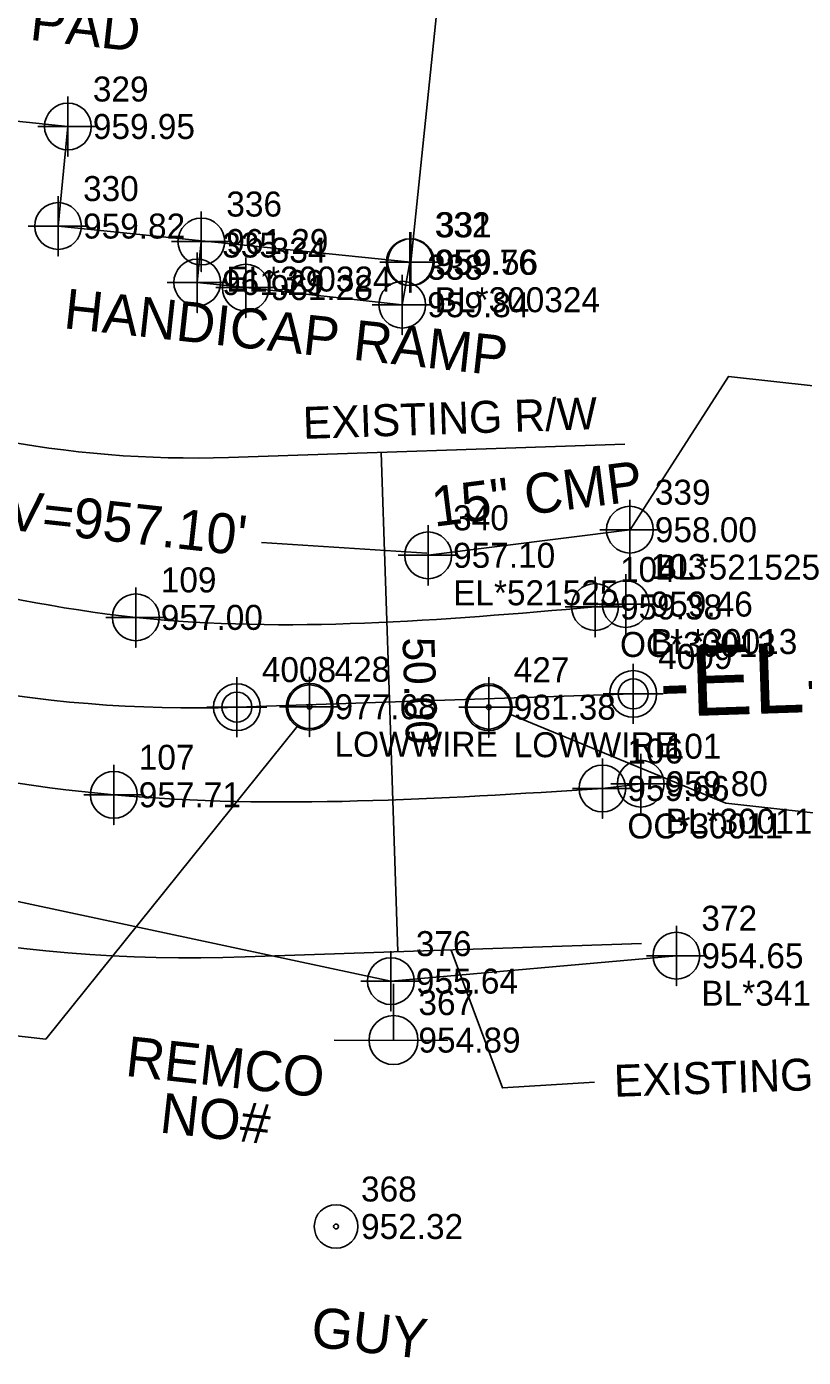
# Model space of a CAD drawing. Extents: x 1150279 to 1151282, y 654632 to 657999.
# Drawn here: x 1150999.3 to 1151077.1, y 657002 to 657135.2 of the extents above; entities that cross this region are included whole.
import ezdxf

# ---------------------------------------------------------------- set-up
doc = ezdxf.new("R2010")
doc.units = 0
for name, color, linetype in [('COGO Default Chain', 7, 'Continuous'), ('COGO Default Curve', 7, 'Continuous'), ('Cogo Default Point CELL', 7, 'Continuous'), ('COGO Default Point Number', 7, 'Continuous'), ('Default Symbol CELL', 7, 'Continuous'), ('Default Symbol Cogo Comment', 7, 'Continuous'), ('Default Symbol Cogo Elevation', 7, 'Continuous'), ('Default Symbol Cogo Number', 7, 'Continuous'), ('Exist Building', 7, 'Continuous'), ('Exist Building Cogo Elevation', 7, 'Continuous'), ('Exist Building Cogo Number', 7, 'Continuous'), ('Exist Building Cogo Point CELL', 7, 'Continuous'), ('Exist Horizontal Alignment', 7, 'Continuous'), ('Exist Horizontal Alignment Direction Label', 7, 'Continuous'), ('Exist Horizontal Alignment Station Label', 7, 'Continuous'), ('Exist Other Culture Anchor (Guy Wire) CELL', 7, 'Continuous'), ('Exist Other Culture Anchor (Guy Wire) Cogo Elevation', 7, 'Continuous'), ('Exist Other Culture Anchor (Guy Wire) Cogo Number', 7, 'Continuous'), ('Exist Other Culture Fence Line', 7, 'Continuous'), ('Exist Other Culture Fence Line Cogo Comment', 7, 'Continuous'), ('Exist Other Culture Fence Line Cogo Elevation', 7, 'Continuous'), ('Exist Other Culture Fence Line Cogo Number', 7, 'Continuous'), ('Exist Other Culture Fence Line Cogo Point CELL', 7, 'Continuous'), ('Exist Right of Way Line', 7, 'Continuous'), ('Exist Right of Way Line Leader', 7, 'Continuous'), ('Exist Right of Way Line Text', 7, 'Continuous'), ('Exist Right of Way Width CELL', 7, 'Continuous'), ('Exist Roads EOP', 7, 'Continuous'), ('Exist Roads EOP Cogo Comment', 7, 'Continuous'), ('Exist Roads EOP Cogo Elevation', 7, 'Continuous'), ('Exist Roads EOP Cogo Number', 7, 'Continuous'), ('Exist Roads EOP Cogo Point CELL', 7, 'Continuous'), ('Exist Roads EOP Other', 7, 'Continuous'), ('Exist Roads EOP Other Cogo Comment', 7, 'Continuous'), ('Exist Roads EOP Other Cogo Elevation', 7, 'Continuous'), ('Exist Roads EOP Other Cogo Number', 7, 'Continuous'), ('Exist Roads EOP Other Cogo Point CELL', 7, 'Continuous'), ('Exist Roads EOP Other Text', 7, 'Continuous'), ('Exist Roads EOP Text', 7, 'Continuous'), ('Exist Structure Minor Pipes CMP 15 Inch', 7, 'Continuous'), ('Exist Structure Minor Pipes CMP 15 Inch Cogo Comment', 7, 'Continuous'), ('Exist Structure Minor Pipes CMP 15 Inch Cogo Elevation', 7, 'Continuous'), ('Exist Structure Minor Pipes CMP 15 Inch Cogo Number', 7, 'Continuous'), ('Exist Structure Minor Pipes CMP 15 Inch Cogo Point CELL', 7, 'Continuous'), ('Exist Structure Minor Pipes CMP 15 Inch Leader', 7, 'Continuous'), ('Exist Structure Minor Pipes CMP 15 Inch Text', 7, 'Continuous'), ('Exist Utilities Other Located Object CELL', 7, 'Continuous'), ('Exist Utilities Other Located Object Leader', 7, 'Continuous'), ('Exist Utilities Power Joint Use Telephone CELL', 7, 'Continuous'), ('Exist Utilities Power Joint Use Telephone Cogo Elevation', 7, 'Continuous'), ('Exist Utilities Power Joint Use Telephone Cogo Number', 7, 'Continuous'), ('Exist Utilities Power Joint Use Telephone Text', 7, 'Continuous')]:
    doc.layers.add(name, color=color, linetype=linetype)

msp = doc.modelspace()

# ---------------------------------------------------------------- linework, layer by layer
at = {"layer": 'COGO Default Chain'}
msp.add_line((1151020.37, 657067.07), (1151060.05, 657068.39), dxfattribs=at)
msp.add_arc((1151016.01, 657196.99), 130, 245.6804, 271.9187, dxfattribs=at)
at = {"layer": 'COGO Default Curve'}
msp.add_arc((1151016.01, 657196.99), 130, 245.6804, 271.9187, dxfattribs=at)
at = {"layer": 'Cogo Default Point CELL'}
for points in [[(1151060.05, 657071.39), (1151060.05, 657068.39)], [(1151020.37, 657070.07), (1151020.37, 657067.07)], [(1151020.37, 657070.07), (1151020.37, 657067.07)], [(1151057.05, 657068.39), (1151060.05, 657068.39)], [(1151060.05, 657068.39), (1151063.05, 657068.39)], [(1151060.05, 657068.39), (1151060.05, 657065.39)], [(1151017.37, 657067.07), (1151020.37, 657067.07)], [(1151017.37, 657067.07), (1151020.37, 657067.07)], [(1151020.37, 657067.07), (1151023.37, 657067.07)], [(1151020.37, 657067.07), (1151020.37, 657064.07)], [(1151020.37, 657067.07), (1151023.37, 657067.07)], [(1151020.37, 657067.07), (1151020.37, 657064.07)]]:
    msp.add_lwpolyline(points, dxfattribs=at)
for centre in [(1151060.05, 657068.39), (1151020.37, 657067.07), (1151020.37, 657067.07)]:
    msp.add_circle(centre, 2.34, dxfattribs=at)
at = {"layer": 'Default Symbol CELL'}
for points in [[(1151027.65, 657070.11), (1151027.65, 657064.11), (1151027.65, 657067.11), (1151030.65, 657067.11), (1151024.65, 657067.11)], [(1151045.59, 657070.06), (1151045.59, 657064.06), (1151045.59, 657067.06), (1151048.59, 657067.06), (1151042.59, 657067.06)]]:
    msp.add_lwpolyline(points, dxfattribs=at)
for centre in [(1151027.65, 657067.11), (1151045.59, 657067.06)]:
    msp.add_circle(centre, 2.34, dxfattribs=at)
at = {"layer": 'Exist Building'}
msp.add_lwpolyline([(1150963.17, 657162.3), (1150962, 657151.2), (1150955.74, 657152.17), (1150954.56, 657141.15), (1150960.94, 657140.6), (1150959.8, 657129.69), (1151003.45, 657125.16), (1151002.47, 657115.2), (1151037.8, 657111.58), (1151043.24, 657164.14)], dxfattribs=at)
at = {"layer": 'Exist Building Cogo Point CELL'}
for points in [[(1151003.45, 657128.16), (1151003.45, 657122.16), (1151003.45, 657125.16), (1151006.45, 657125.16), (1151000.45, 657125.16)], [(1151002.47, 657118.2), (1151002.47, 657112.2), (1151002.47, 657115.2), (1151005.47, 657115.2), (1150999.47, 657115.2)], [(1151037.8, 657114.58), (1151037.8, 657108.58), (1151037.8, 657111.58), (1151040.8, 657111.58), (1151034.8, 657111.58)]]:
    msp.add_lwpolyline(points, dxfattribs=at)
for centre in [(1151003.45, 657125.16), (1151002.47, 657115.2), (1151037.8, 657111.58)]:
    msp.add_circle(centre, 2.34, dxfattribs=at)
at = {"layer": 'Exist Horizontal Alignment'}
msp.add_line((1151020.37, 657067.07), (1151060.05, 657068.39), dxfattribs=at)
msp.add_arc((1151016.01, 657196.99), 130, 245.6804, 271.9187, dxfattribs=at)
at = {"layer": 'Exist Horizontal Alignment Station Label'}
for centre in [(1151060.05, 657068.39), (1151020.37, 657067.07)]:
    msp.add_circle(centre, 1.5, dxfattribs=at)
at = {"layer": 'Exist Other Culture Anchor (Guy Wire) CELL'}
for radius in [2.18, 0.24]:
    msp.add_circle((1151030.3, 657015.11), radius, dxfattribs=at)
at = {"layer": 'Exist Other Culture Fence Line'}
msp.add_lwpolyline([(1151064.38, 657042.2), (1151035.79, 657039.66), (1150986.53, 657050.15), (1150941.42, 657063.2), (1150898.39, 657078.65), (1150854.86, 657094.99), (1150825.03, 657100.53), (1150812.46, 657091.59), (1150835.17, 657043.74), (1150852.72, 657007.43)], dxfattribs=at)
at = {"layer": 'Exist Other Culture Fence Line Cogo Point CELL'}
for points in [[(1151064.38, 657045.2), (1151064.38, 657039.2), (1151064.38, 657042.2), (1151067.38, 657042.2), (1151061.38, 657042.2)], [(1151035.79, 657042.66), (1151035.79, 657036.66), (1151035.79, 657039.66), (1151038.79, 657039.66), (1151032.79, 657039.66)]]:
    msp.add_lwpolyline(points, dxfattribs=at)
for centre in [(1151064.38, 657042.2), (1151035.79, 657039.66)]:
    msp.add_circle(centre, 2.34, dxfattribs=at)
at = {"layer": 'Exist Right of Way Line'}
for p, q in [((1151019.53, 657092.05), (1151059.22, 657093.38)), ((1151021.2, 657042.08), (1151060.89, 657043.41))]:
    msp.add_line(p, q, dxfattribs=at)
for radius in [105, 155]:
    msp.add_arc((1151016.01, 657196.99), radius, 245.6804, 271.9187, dxfattribs=at)
at = {"layer": 'Exist Right of Way Line Leader'}
msp.add_lwpolyline([(1151041.84, 657042.77), (1151046.96, 657028.97), (1151056.17, 657029.54)], dxfattribs=at)
at = {"layer": 'Exist Right of Way Width CELL'}
for p in [(1151034.81, 657092.56), (1151036.48, 657042.59)]:
    msp.add_line(p, (1151035.67, 657066.81), dxfattribs=at)
at = {"layer": 'Exist Roads EOP'}
for p, q in [((1151059.3, 657077.38), (1151056.23, 657077.09)), ((1151060.81, 657059.41), (1151056.97, 657058.93))]:
    msp.add_line(p, q, dxfattribs=at)
for points in [[(1151056.23, 657077.09), (1151010.25, 657076.05), (1150965.32, 657087.79), (1150920.52, 657109.03), (1150919.16, 657109.82)], [(1151056.97, 657058.93), (1151008.05, 657058.3), (1150957.78, 657070.1), (1150911.09, 657090.11), (1150910.09, 657090.54)]]:
    msp.add_spline(points, degree=3, dxfattribs=at)
at = {"layer": 'Exist Roads EOP Cogo Point CELL'}
for points in [[(1151056.23, 657080.09), (1151056.23, 657074.09), (1151056.23, 657077.09), (1151059.23, 657077.09), (1151053.23, 657077.09)], [(1151059.3, 657080.38), (1151059.3, 657074.38), (1151059.3, 657077.38), (1151062.3, 657077.38), (1151056.3, 657077.38)], [(1151010.25, 657079.05), (1151010.25, 657073.05), (1151010.25, 657076.05), (1151013.25, 657076.05), (1151007.25, 657076.05)], [(1151056.97, 657061.93), (1151056.97, 657055.93), (1151056.97, 657058.93), (1151059.97, 657058.93), (1151053.97, 657058.93)], [(1151060.81, 657062.41), (1151060.81, 657056.41), (1151060.81, 657059.41), (1151063.81, 657059.41), (1151057.81, 657059.41)], [(1151008.05, 657061.3), (1151008.05, 657055.3), (1151008.05, 657058.3), (1151011.05, 657058.3), (1151005.05, 657058.3)]]:
    msp.add_lwpolyline(points, dxfattribs=at)
for centre in [(1151056.23, 657077.09), (1151059.3, 657077.38), (1151010.25, 657076.05), (1151008.05, 657058.3), (1151056.97, 657058.93), (1151060.81, 657059.41)]:
    msp.add_circle(centre, 2.34, dxfattribs=at)
at = {"layer": 'Exist Roads EOP Other'}
msp.add_lwpolyline([(1151037.68, 657111.58), (1151036.93, 657107.33), (1151021.26, 657109.04), (1151016.4, 657109.55), (1151016.81, 657113.65)], dxfattribs=at)
at = {"layer": 'Exist Roads EOP Other Cogo Point CELL'}
for points in [[(1151016.81, 657116.65), (1151016.81, 657110.65), (1151016.81, 657113.65), (1151019.81, 657113.65), (1151013.81, 657113.65)], [(1151037.68, 657114.58), (1151037.68, 657108.58), (1151037.68, 657111.58), (1151040.68, 657111.58), (1151034.68, 657111.58)], [(1151016.4, 657112.55), (1151016.4, 657106.55), (1151016.4, 657109.55), (1151019.4, 657109.55), (1151013.4, 657109.55)], [(1151021.26, 657112.04), (1151021.26, 657106.04), (1151021.26, 657109.04), (1151024.26, 657109.04), (1151018.26, 657109.04)], [(1151036.93, 657110.33), (1151036.93, 657104.33), (1151036.93, 657107.33), (1151039.93, 657107.33), (1151033.93, 657107.33)]]:
    msp.add_lwpolyline(points, dxfattribs=at)
for centre in [(1151016.81, 657113.65), (1151037.68, 657111.58), (1151016.4, 657109.55), (1151021.26, 657109.04), (1151036.93, 657107.33)]:
    msp.add_circle(centre, 2.34, dxfattribs=at)
at = {"layer": 'Exist Structure Minor Pipes CMP 15 Inch'}
msp.add_line((1151059.72, 657084.82), (1151039.52, 657082.26), dxfattribs=at)
at = {"layer": 'Exist Structure Minor Pipes CMP 15 Inch Cogo Point CELL'}
for points in [[(1151059.72, 657087.82), (1151059.72, 657081.82), (1151059.72, 657084.82), (1151062.72, 657084.82), (1151056.72, 657084.82)], [(1151039.52, 657085.26), (1151039.52, 657079.26), (1151039.52, 657082.26), (1151042.52, 657082.26), (1151036.52, 657082.26)]]:
    msp.add_lwpolyline(points, dxfattribs=at)
for centre in [(1151059.72, 657084.82), (1151039.52, 657082.26)]:
    msp.add_circle(centre, 2.34, dxfattribs=at)
at = {"layer": 'Exist Structure Minor Pipes CMP 15 Inch Leader'}
msp.add_line((1151039.38, 657082.47), (1151022.85, 657083.53), dxfattribs=at)
msp.add_lwpolyline([(1151059.75, 657084.81), (1151069.59, 657100.15), (1151078.38, 657099.18)], dxfattribs=at)
at = {"layer": 'Exist Utilities Other Located Object CELL'}
for centre, radius in [((1151027.65, 657067.11), 2.18), ((1151045.59, 657067.06), 2.18), ((1151027.65, 657067.11), 0.24), ((1151045.59, 657067.06), 0.24)]:
    msp.add_circle(centre, radius, dxfattribs=at)
at = {"layer": 'Exist Utilities Other Located Object Leader'}
for points in [[(1151047.69, 657066.38), (1151069.32, 657057.45), (1151082.27, 657056.02)], [(1151026.43, 657065.18), (1151001.23, 657033.86), (1150989.95, 657035.11)]]:
    msp.add_lwpolyline(points, dxfattribs=at)
at = {"layer": 'Exist Utilities Power Joint Use Telephone CELL'}
msp.add_line((1151036.05, 657033.76), (1151036.05, 657033.76), dxfattribs=at)
msp.add_lwpolyline([(1151030.11, 657033.76), (1151041.45, 657033.72), (1151036.05, 657033.74), (1151036.05, 657039.38)], dxfattribs=at)
msp.add_circle((1151036.05, 657033.76), 2.45, dxfattribs=at)

# ---------------------------------------------------------------- texts
at = {"layer": 'COGO Default Point Number'}
for s, p in [('4009', (1151062.55, 657070.89)), ('4008', (1151022.87, 657069.57))]:
    msp.add_text(s, height=2.5, dxfattribs=at).set_placement(p)
at = {"layer": 'Default Symbol Cogo Comment'}
for p in [(1151030.15, 657062.11), (1151048.09, 657062.06)]:
    msp.add_text('LOWWIRE', height=2.5, dxfattribs=at).set_placement(p)
at = {"layer": 'Default Symbol Cogo Elevation'}
for s, p in [('977.68', (1151030.15, 657065.86)), ('981.38', (1151048.09, 657065.81))]:
    msp.add_text(s, height=2.5, dxfattribs=at).set_placement(p)
at = {"layer": 'Default Symbol Cogo Number'}
for s, p in [('428', (1151030.15, 657069.61)), ('427', (1151048.09, 657069.56))]:
    msp.add_text(s, height=2.5, dxfattribs=at).set_placement(p)
at = {"layer": 'Exist Building Cogo Elevation'}
for s, p in [('959.95', (1151005.95, 657123.91)), ('959.82', (1151004.97, 657113.95)), ('959.56', (1151040.3, 657110.33))]:
    msp.add_text(s, height=2.5, dxfattribs=at).set_placement(p)
at = {"layer": 'Exist Building Cogo Number'}
for s, p in [('329', (1151005.95, 657127.66)), ('330', (1151004.97, 657117.7)), ('331', (1151040.3, 657114.08))]:
    msp.add_text(s, height=2.5, dxfattribs=at).set_placement(p)
at = {"layer": 'Exist Horizontal Alignment Direction Label'}
msp.add_text('-EL-', height=7, rotation=1.9187, dxfattribs=at).set_placement((1151062.75, 657066.07))
at = {"layer": 'Exist Other Culture Anchor (Guy Wire) Cogo Elevation'}
msp.add_text('952.32', height=2.5, dxfattribs=at).set_placement((1151032.8, 657013.86))
at = {"layer": 'Exist Other Culture Anchor (Guy Wire) Cogo Number'}
msp.add_text('368', height=2.5, dxfattribs=at).set_placement((1151032.8, 657017.61))
at = {"layer": 'Exist Other Culture Fence Line Cogo Comment'}
msp.add_text('BL*341028', height=2.5, dxfattribs=at).set_placement((1151066.88, 657037.2))
at = {"layer": 'Exist Other Culture Fence Line Cogo Elevation'}
for s, p in [('954.65', (1151066.88, 657040.95)), ('955.64', (1151038.29, 657038.41))]:
    msp.add_text(s, height=2.5, dxfattribs=at).set_placement(p)
at = {"layer": 'Exist Other Culture Fence Line Cogo Number'}
for s, p in [('372', (1151066.88, 657044.7)), ('376', (1151038.29, 657042.16))]:
    msp.add_text(s, height=2.5, dxfattribs=at).set_placement(p)
at = {"layer": 'Exist Right of Way Line Text'}
for p in [(1151027.03, 657093.9), (1151058.17, 657028.08)]:
    msp.add_text('EXISTING R/W', height=3.2, rotation=1.9187, dxfattribs=at).set_placement(p)
at = {"layer": 'Exist Right of Way Width CELL'}
msp.add_text("50.00'", height=3.2, rotation=271.9187, dxfattribs=at).set_placement((1151036.95, 657074.02))
at = {"layer": 'Exist Roads EOP Cogo Comment'}
for s, p in [('OC*30013', (1151058.73, 657072.09)), ('BL*30013', (1151061.8, 657072.38)), ('BL*30011', (1151063.31, 657054.41)), ('OC*30011', (1151059.47, 657053.93))]:
    msp.add_text(s, height=2.5, dxfattribs=at).set_placement(p)
at = {"layer": 'Exist Roads EOP Cogo Elevation'}
for s, p in [('959.38', (1151058.73, 657075.84)), ('959.46', (1151061.8, 657076.13)), ('957.00', (1151012.75, 657074.8)), ('959.80', (1151063.31, 657058.16)), ('957.71', (1151010.55, 657057.05)), ('959.66', (1151059.47, 657057.68))]:
    msp.add_text(s, height=2.5, dxfattribs=at).set_placement(p)
at = {"layer": 'Exist Roads EOP Cogo Number'}
for s, p in [('104', (1151058.73, 657079.59)), ('103', (1151061.8, 657079.88)), ('109', (1151012.75, 657078.55)), ('107', (1151010.55, 657060.8)), ('106', (1151059.47, 657061.43)), ('101', (1151063.31, 657061.91))]:
    msp.add_text(s, height=2.5, dxfattribs=at).set_placement(p)
at = {"layer": 'Exist Roads EOP Other Cogo Comment'}
for s, p in [('EL*300324', (1151019.31, 657108.65)), ('BL*300324', (1151040.18, 657106.58))]:
    msp.add_text(s, height=2.5, dxfattribs=at).set_placement(p)
at = {"layer": 'Exist Roads EOP Other Cogo Elevation'}
for s, p in [('961.29', (1151019.31, 657112.4)), ('959.76', (1151040.18, 657110.33)), ('961.29', (1151018.9, 657108.3)), ('961.28', (1151023.76, 657107.79)), ('959.84', (1151039.43, 657106.08))]:
    msp.add_text(s, height=2.5, dxfattribs=at).set_placement(p)
at = {"layer": 'Exist Roads EOP Other Cogo Number'}
for s, p in [('336', (1151019.31, 657116.15)), ('332', (1151040.18, 657114.08)), ('335', (1151018.9, 657112.05)), ('334', (1151023.76, 657111.54)), ('333', (1151039.43, 657109.83))]:
    msp.add_text(s, height=2.5, dxfattribs=at).set_placement(p)
at = {"layer": 'Exist Roads EOP Other Text'}
msp.add_text('HANDICAP RAMP', height=4, rotation=353.7927, dxfattribs=at).set_placement((1151002.93, 657104.99))
at = {"layer": 'Exist Roads EOP Text'}
msp.add_text('CONC. PAD', height=4, rotation=353.6867, dxfattribs=at).set_placement((1150980.94, 657135.9))
at = {"layer": 'Exist Structure Minor Pipes CMP 15 Inch Cogo Comment'}
for s, p in [('BL*521525', (1151062.22, 657079.82)), ('EL*521525', (1151042.02, 657077.26))]:
    msp.add_text(s, height=2.5, dxfattribs=at).set_placement(p)
at = {"layer": 'Exist Structure Minor Pipes CMP 15 Inch Cogo Elevation'}
for s, p in [('958.00', (1151062.22, 657083.57)), ('957.10', (1151042.02, 657081.01))]:
    msp.add_text(s, height=2.5, dxfattribs=at).set_placement(p)
at = {"layer": 'Exist Structure Minor Pipes CMP 15 Inch Cogo Number'}
for s, p in [('339', (1151062.22, 657087.32)), ('340', (1151042.02, 657084.76))]:
    msp.add_text(s, height=2.5, dxfattribs=at).set_placement(p)
at = {"layer": 'Exist Structure Minor Pipes CMP 15 Inch Text'}
for s, rotation, p in [('15" CMP', 7.2171, (1151040.13, 657085.11)), ("INV=957.10'", 353.6867, (1150991.87, 657085.44))]:
    msp.add_text(s, height=4, rotation=rotation, dxfattribs=at).set_placement(p)
at = {"layer": 'Exist Utilities Power Joint Use Telephone Cogo Elevation'}
msp.add_text('954.89', height=2.5, dxfattribs=at).set_placement((1151038.55, 657032.51))
at = {"layer": 'Exist Utilities Power Joint Use Telephone Cogo Number'}
msp.add_text('367', height=2.5, dxfattribs=at).set_placement((1151038.55, 657036.26))
at = {"layer": 'Exist Utilities Power Joint Use Telephone Text'}
for s, p in [('REMCO', (1151009.11, 657030.19)), ('NO#', (1151012.54, 657024.53)), ('GUY', (1151027.67, 657003.12))]:
    msp.add_text(s, height=4, rotation=353.6867, dxfattribs=at).set_placement(p)

doc.saveas('drawing.dxf')
